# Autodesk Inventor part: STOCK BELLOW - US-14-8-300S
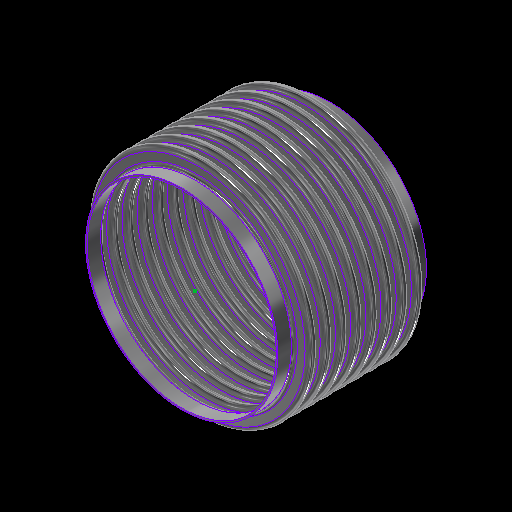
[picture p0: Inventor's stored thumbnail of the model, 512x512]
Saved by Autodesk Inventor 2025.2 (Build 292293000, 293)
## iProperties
Category: 16 GA (0.060 THICK)
RuleStatus: InUse
Created: 2024-01
Part Number: STOCK BELLOW - US-14-8-300S
Project: =STOCK BELLOWS: <Stock Number><SFILL>
Material: ASTM A240-304
Description: =STOCK BELLOWS: <Stock Number>, <SID_> I.D., <SOD_> O.D., <SPLY_> PLY, <Category>, <SNET_CONS> CONS.<PITCH_><STANGENT_> TANGENT<SFILL>
Document SubType Name: Sheet Metal
Designer: GS
Stock Number: U.S-14-8-300S
Surface Area: 15703.3 cm^2
Volume: 2361.78 cm^3
Sheet Metal Rule: Default
Appearance: STAINLESS STEEL
Mass: 19029.5 g
Density: 8.05729 g/cm^3
THK: 0.036
ID: 3.500
OD: 4.250
CONS_: 2
PITCH: 0.500
TANGENT: 0.500
BELLOWS_UPSET: 0.000
d79: 1.000
d82: 1.000
d83: 26.000
d84: 24.000
d174: 8
d214: 8
STHK_: 0.060
SID_: 14.000
SOD_: 16.500
SPITCH_: 1.125
STANGENT__: 1.000
SBELLOWS_UPSET_: 0.000
SDIFF_TAN: 1.000
d252: 2
d275: 2
d287: 0.050
d289: 0.500
d290: 0.000
SOD_NECK: 14 1/4
PLY: 1
PSET: 4.178
PBAR: 1.035
COUNTER: 1.500
NET_TUBE: 3.071
CONS: 2
S_CONS: 0
NET_CONS: 2
ID_M: 88.90 mm
OD_M: 107.95 mm
THK_M: 0.91 mm
ID_U: 3.500 in
OD_U: 4.250 in
THK_U: 0.036 in
TANGENT2: 0.500
TAN_TO_TAN: 1.000 in
d80: 2.571
d81: 10
SID: 2.375
SCONS_: 8
SPITCH: 0.250
STANGENT_: 1.000
SBELLOWS_UPSET: 0.000
SNET_CONS: 8
SS_CONS: 0
SCONS: 8
d190: 8
d191: 1
d192: 1
d193: 8
d194: 0
SIZE: 14.00
PRESSURE: 300
d230: 8
STANGENT: 4.000
SPLY_: 2
d233: 8
d234: 0
d263: 2
d265: 1
d268: 2
d269: 0
d286: 2
d288: 1
d291: 2
d292: 0
SREROLL: 0.750
BLETP: 0.000 ul
PRES_Copy: 85
MATTABLE: 20 GA (0.036 THICK)
PART_NUMBER: U.S-14-8-300S
PITCH_: =, <SPITCH_> PITCH,
CFILL: .
SFILL: .
MESH: ,
COMP: 1.55
EXT: 0.78
LAT: 0.30
ANG: 573
ASR: 8185
LSR: 35251
ANSR: 4153
PRES: 300
COMPM: 15.5
EXTM: 7.75
LATM: 3.00
ASRM: 1433.439
PRESM: 20.684
LSRM: 6173.508
ANSRM: 727.315
TEMPMIN: 20
TEMPMAX: 800
TEMPMINM: -7
TEMPMAXM: 427
WEIGHTM: 19.030
WEIGHT: 41.953
Author: GS
Keywords: 20 GA (0.036 THICK)
Comments: =STOCK BELLOW - <STOCK NUMBER>
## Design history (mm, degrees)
sketch "Sketch2"
  geometry: L1 (0, -177.245)-(0, 562.856) reference; L2 (45.364, 0)-(44.45, 0); L3 (48.082, -2.718)-(50.343, -2.718); L4 (48.082, -3.632)-(50.343, -3.632); L5 (50.343, -9.982)-(48.082, -9.982); L6 (50.343, -9.068)-(48.082, -9.068); L7 (45.364, -12.7)-(44.45, -12.7); L8 (48.082, 0)-(48.082, -12.7); L9 (50.343, -6.35)-(53.975, -6.35); L10 (44.45, 0)-(44.45, -12.7); L11 (20.376, 102.841)-(20.376, 101.926); L12 (58.262, 457.127)-(58.262, 349.177); L13 (58.262, 444.427)-(58.262, 336.477); L14 (93.133, -58.817)-(93.133, -71.517); L15 (118.746, -66.401)-(118.746, -66.401); L16 (50.343, -9.068)-(50.343, -9.982); L17 (48.082, -9.068)-(48.082, -9.982); L18 (48.082, -9.525)-(50.343, -9.525); L19 (53.975, 0)-(53.975, -12.7); L20 (-50.343, -9.068)-(-50.343, -9.982); L21 (-50.343, -2.718)-(-48.082, -2.718); L22 (-50.343, -3.632)-(-48.082, -3.632); L23 (-48.082, -9.068)-(-50.343, -9.068); L24 (-50.343, -9.525)-(-48.082, -9.525); L25 (-48.082, -9.982)-(-50.343, -9.982); L26 (-48.082, -9.068)-(-48.082, -9.982); L27 (-44.45, 0.653)-(-44.45, -12.047); L28 (-48.082, -6.35)-(-44.45, -6.35); L29 (-50.343, 0.653)-(-50.343, -12.7); L30 (-53.061, 0)-(-53.975, 0); L31 (-53.975, 0)-(-53.975, -12.7); L32 (-53.061, -12.7)-(-53.975, -12.7); A1 r 2.718 centre (48.082, 0) between (45.364, 0) and (48.082, -2.718); A2 r 3.632 centre (48.082, 0) between (44.45, 0) and (48.082, -3.632); A3 r 3.632 centre (50.343, -6.35) between (50.343, -9.982) and (50.343, -2.718); A4 r 2.718 centre (50.343, -6.35) between (50.343, -9.068) and (50.343, -3.632); A5 r 2.718 centre (48.082, -12.7) between (48.082, -9.982) and (45.364, -12.7); A6 r 3.632 centre (48.082, -12.7) between (48.082, -9.068) and (44.45, -12.7); A7 r 3.175 centre (50.343, -6.35) between (50.343, -9.525) and (53.518, -6.35); A8 r 3.175 centre (48.082, -12.7) between (48.082, -9.525) and (44.907, -12.7); A9 r 2.718 centre (-50.343, -12.7) between (-50.343, -9.982) and (-53.061, -12.7); A10 r 2.718 centre (-48.082, -6.35) between (-48.082, -9.068) and (-48.082, -3.632); A11 r 3.175 centre (-48.082, -6.35) between (-48.082, -9.525) and (-44.907, -6.35); A12 r 3.632 centre (-48.082, -6.35) between (-48.082, -9.982) and (-48.082, -2.718); A13 r 3.175 centre (-50.343, -12.7) between (-50.343, -9.525) and (-53.518, -12.7); A14 r 3.632 centre (-50.343, -12.7) between (-50.343, -9.068) and (-53.975, -12.7); A15 r 2.718 centre (-50.343, 0) between (-53.061, 0) and (-50.343, -2.718); A16 r 3.632 centre (-50.343, 0) between (-53.975, 0) and (-50.343, -3.632); 10 further points
  constraints: 62 end point, 38 point on circle, 20 tangent, 16 centre point, 12 parallel, 9 midpoint, 7 vertical, 6 coincident, 6 concentric, 6 point on line, 4 equal radius, 4 perpendicular, 3 horizontal, 1 collinear, 1 horizontal alignment, 10 other
  dimensions: "THK" = 0.9144 distance of L11.start L11.end; "ID" = 88.9 distance of L11.end point (20.376, 13.026); "OD" = 107.95 distance of L12.start L12.end; "PITCH" = 12.7 distance of L12.start L13.start; "TANGENT" = 12.7 distance of L14.start L14.end; "BELLOWS_UPSET" = 0 distance of L15.start L15.end; "d43" = 88.9 diameter of L10 L1 (= ID); "d44" = 107.95 diameter of L9.end L1 (= OD); "d45" = 0.9144 distance between parallel lines of L5 L6 (computed from THK, PLY); "d46" = 3.6322 radius of A3 (computed from PITCH, THK, PLY); "UPSET_PITCH" = 12.7 distance of L2.end L7.end (derived); "SIDEWALL_ANGLE" = 360 deg dimension on L3 L9 (derived); "CON_GAP" = 5.4356 distance of point (48.082, -9.068) point (48.082, -3.632) (derived); "TAN1" = 4.98728 dimension on A8 (derived); "TAN2" = 4.98728 dimension on A7 (derived); "LEG1" = 2.2606 distance of L18.start L18.end (derived); "d278" = 0.9144 distance between parallel lines of L25 L23 (derived); "d279" = 3.6322 radius of A12 (derived); "d280" = 12.7 distance of L30.end L31.end (derived); "d281" = 360 deg dimension on L21 L28 (derived); "d282" = 5.4356 distance of point (-50.343, -9.068) point (-50.343, -3.632) (derived); "d283" = 4.98728 dimension on A13 (derived); "d284" = 4.98728 dimension on A11 (derived); "d285" = 2.2606 distance of L24.start L24.end (derived); "d293" = 88.9 diameter of L27 L1 (derived); "d294" = 107.95 diameter of L31 L1 (derived)
  node "Sketch Rectangular Pattern1" dims "d31" = 25.4, "ID" = 88.9
  node "Sketch Rectangular Pattern2" dims "d39" = 25.4, "PITCH" = 12.7
revolve "CONS" stored, may be unused: angle "d48" = 90 deg
node "BELLOW MIDPLANE"
pattern_linear "Rectangular Pattern2" dims "d52" = 12.7 (= UPSET_PITCH)
sketch "Sketch5"
  geometry: C1 r 45.364 at (0, 0) reference; C2 r 44.45 at (0, 0) reference
extrude "TANGENT" new body sketch "Sketch5" distance "d53" = 12.7 (= TANGENT); taper "d54" = 0 deg
revolve "SAMETAN" stored, may be unused: angle "d65" = 90 deg
revolve "DIFFTAN" stored, may be unused: angle "d70" = 90 deg
sketch "Sketch9"
  geometry: L1 (53.319, 0)-(-53.319, 0) reference; L2 (0, -17.78)-(0, 17.78) reference; L3 (38.085, 0)-(-38.085, 0); L4 (38.085, -11.906)-(38.085, 11.906); L5 (25.385, -11.906)-(25.385, 11.906); L6 (13.15, 11.906)-(13.15, -11.906); L7 (-25.385, -11.906)-(-25.385, 11.906); L8 (-38.085, -11.906)-(-38.085, 11.906); L9 (37.291, -11.906)-(37.291, 11.906); L10 (38.085, -11.906)-(37.291, -11.906); L11 (38.085, 11.906)-(37.291, 11.906); L12 (13.546, 11.906)-(12.753, 11.906); L13 (12.753, 11.906)-(12.753, -11.906); L14 (12.753, -11.906)-(13.546, -11.906); L15 (13.546, -11.906)-(13.546, 11.906); L16 (-13.546, 11.906)-(-13.546, -11.906); L17 (-13.15, 11.906)-(-13.15, -11.906); L18 (-13.546, -11.906)-(-12.753, -11.906); L19 (-12.753, -11.906)-(-12.753, 11.906); L20 (-12.753, 11.906)-(-13.546, 11.906); L21 (-38.085, -11.906)-(-37.291, -11.906); L22 (-37.291, -11.906)-(-37.291, 11.906); L23 (-37.291, 11.906)-(-38.085, 11.906); L24 (-38.085, 11.906)-(-38.085, -11.906); L25 (38.085, -0.397)-(-38.085, -0.397); L26 (-38.085, -0.397)-(-38.085, 0.397); L27 (-38.085, 0.397)-(38.085, 0.397); L28 (38.085, 0.397)-(38.085, -0.397); L29 (-38.085, 11.906)-(38.085, 11.906); L30 (38.085, 11.906)-(38.085, 12.7); L31 (38.085, 12.7)-(-38.085, 12.7); L32 (-38.085, 12.7)-(-38.085, 11.906); L33 (38.085, -11.906)-(-38.085, -11.906); L34 (-38.085, -11.906)-(-38.085, -12.7); L35 (-38.085, -12.7)-(38.085, -12.7); L36 (38.085, -12.7)-(38.085, -11.906); 30 further points
  constraints: 68 end point, 13 midpoint, 13 parallel, 8 horizontal, 7 perpendicular, 6 equal length, 3 point on line, 2 vertical, 14 other
  dimensions: "d115" = 23.8125 distance of L4.start L4.end (derived); "d116" = 12.7 distance between parallel lines of L4 L5 (derived); "d117" = 12.23516 distance between parallel lines of L5 L6 (derived); "d125" = 38.53427 distance between parallel lines of L7 L6 (derived); "d127" = 12.7 distance between parallel lines of L8 L7 (derived); "d128" = 24.93516 distance between parallel lines of L6 L4 (derived); "d130" = 76.16943 distance between parallel lines of L8 L4 (derived); "RULER_THK" = 0.79375 distance between parallel lines of L4 L9; "d135" = 0.79375 distance of L13.end L14.end (derived); "d138" = 26.29911 distance of L13.end L16.end (derived); "d143" = 0.79375 distance of L22.end L8.end (derived); "d144" = 0.79375 distance between parallel lines of L27 L25 (derived)
extrude "RULER" join sketch "Sketch9" distance "d149" = 0.79375 (derived); taper "d150" = 0 deg
extrude "BARS" join sketch "Sketch9" distance "d151" = 0.79375 (derived); taper "d152" = 0 deg
pattern_linear "Rectangular Pattern4" dims "d155" = 26.29911 (derived)
sketch "Sketch13"
  geometry: L1 (93.149, -52.467)-(93.149, -77.867); L2 (180.848, 0)-(177.8, 0); L3 (180.848, -28.575)-(177.8, -28.575); L4 (200.882, -22.955)-(186.468, -22.955); L5 (200.882, -19.907)-(186.468, -19.907); L6 (200.882, -14.287)-(209.55, -14.287); L7 (186.468, -5.62)-(200.882, -5.62); L8 (186.468, 0)-(186.468, -28.575); L9 (177.8, 0)-(177.8, -28.575); L10 (58.254, -77.331)-(58.254, -496.431); L11 (58.254, -105.906)-(58.254, -525.006); L12 (58.254, -163.056)-(58.254, -582.156); L13 (58.254, -191.631)-(58.254, -610.731); L14 (58.254, -220.206)-(58.254, -639.306); L15 (58.254, -248.781)-(58.254, -667.881); L16 (58.254, -277.356)-(58.254, -696.456); L17 (58.254, -134.481)-(58.254, -553.581); L18 (20.376, 103.45)-(20.376, 101.926); L19 (186.468, -8.668)-(200.882, -8.668); L20 (0, -856.437)-(0, 263.431) reference; L21 (-41.91, 0)-(251.46, 0) reference; A1 r 5.62 centre (186.468, 0) between (180.848, 0) and (186.468, -5.62); A2 r 5.62 centre (186.468, -28.575) between (186.468, -22.955) and (180.848, -28.575); A3 r 8.668 centre (186.468, -28.575) between (186.468, -19.907) and (177.8, -28.575); A4 r 5.62 centre (200.882, -14.287) between (200.882, -19.907) and (200.882, -8.668); A5 r 8.668 centre (200.882, -14.287) between (200.882, -22.955) and (200.882, -5.62); A6 r 8.668 centre (186.468, 0) between (177.8, 0) and (186.468, -8.668); 6 further points; 1 other entity
  constraints: 38 end point, 15 point on circle, 9 tangent, 6 centre point, 6 parallel, 5 vertical alignment, 4 point on line, 4 vertical, 3 coincident, 3 concentric, 2 collinear, 2 equal radius, 1 horizontal, 1 perpendicular, 23 other
  dimensions: "SBELLOWS_UPSET_" = 0 distance of point (118.762, -66.401) point (118.762, -66.401); "STOTAL_THK_BELLOW__" = 3.048 distance between parallel lines of L4 L5 (derived); "d224" = 8.66775 radius of A5 (derived); "d225" = 28.575 distance of L2.end L3.end (derived); "SSIDEWALL_ANGLE_" = 360 deg dimension on L7 L6 (derived); "SSCON_GAP_" = 11.2395 distance of point (186.468, -19.907) point (186.468, -8.668) (derived); "d235" = 355.6 diameter of L9 L20 (derived); "d236" = 419.1 diameter of L6.end L20 (derived)
  node "Sketch Rectangular Pattern4" dims "d228" = 25.4
  node "Sketch Rectangular Pattern5" dims "d229" = 25.4
revolve "SBELLOW" stored, may be unused: angle "d197" = 90 deg
pattern_linear "Rectangular Pattern5" dims "d204" = 28.575 (derived)
revolve "STANGENT" stored, may be unused: angle "d240" = 90 deg
revolve "SSAMETAN" stored, may be unused: angle "d241" = 90 deg
revolve "SDIFFTAN" stored, may be unused: angle "d246" = 90 deg
revolve "INVCON" stored, may be unused: angle "d295" = 90 deg
pattern_linear "Rectangular Pattern6" dims "d298" = 12.7 (derived)
revolve "INVTANGENT" stored, may be unused: angle "d302" = 90 deg
revolve "INVSAMETAN" stored, may be unused: angle "d307" = 90 deg
revolve "INVDIFFTAN" stored, may be unused: angle "d312" = 90 deg
sketch "ID BELLOW MOUNT CALC"
  geometry: L1 (44.45, 0)-(38.1, 0); L2 (38.1, 0)-(38.1, 12.7); L3 (38.1, 12.7)-(44.45, 12.7); L4 (44.45, 12.7)-(44.45, 0); L5 (36.513, 12.7)-(35.598, 12.7); L6 (35.598, 12.7)-(35.598, 0); L7 (35.598, 0)-(36.513, 0); L8 (36.513, 0)-(36.513, 12.7); L9 (0, -2.54)-(0, 15.24) reference; L10 (-8.89, 0)-(53.34, 0) reference; 1 further point
  constraints: 16 end point, 5 parallel, 2 collinear, 2 horizontal, 2 perpendicular
  dimensions: "d314" = 12.7 distance of L5.end L6.end (derived); "d315" = 0.9144 distance of L5.start L5.end (derived); "IG" = 1.5875 distance between parallel lines of L2 L8; "PIPE_OD" = 88.9 diameter of L4 L9; "PIPE_WALL" = 6.35 distance of L2.end L3.end; "ID_MT_BELLOW" = 71.1962 diameter of L6 L9 (derived)
revolve "CFILL" stored, may be unused: angle "d320" = 90 deg
pattern_linear "Rectangular Pattern7" dims "d323" = 12.7 (derived)
revolve "SFILL" stored, may be unused: angle "d324" = 90 deg
pattern_linear "Rectangular Pattern8" dims "d327" = 28.575 (derived)
node "STOCK BELLOW MIDPLANE"
node "BELLOW"
sketch "Sketch6"
  geometry: L1 (-12.7, 45.364)-(0, 45.364); L2 (0, 45.364)-(0, 44.45); L3 (0, 44.45)-(-12.7, 44.45); L4 (-12.7, 44.45)-(-12.7, 45.364); L5 (10.16, 0)-(-60.96, 0) reference; L6 (-38.1, -89.422)-(-38.1, 153.44) reference; 1 further point
  constraints: 8 end point, 2 parallel, 1 horizontal, 1 perpendicular
  dimensions: "d61" = 12.7 distance of L2.end L3.end (derived); "d62" = 0.9144 distance of L1.end L2.end (derived); "d63" = 88.9 diameter of L3 L5 (derived); "d64" = 25.4 distance between parallel lines of L4 L6 (derived)
sketch "Sketch12"
  geometry: 1 further point
sketch "Sketch14"
  geometry: L1 (-25.4, 180.848)-(0, 180.848); L2 (0, 180.848)-(0, 177.8); L3 (0, 177.8)-(-25.4, 177.8); L4 (-25.4, 177.8)-(-25.4, 180.848); L5 (5.08, 0)-(-30.48, 0) reference; L6 (0, -36.17)-(0, 217.018) reference; 1 further point
  constraints: 8 end point, 2 parallel, 1 collinear, 1 horizontal, 1 perpendicular
  dimensions: "d237" = 3.048 distance of L3.end L1.start (derived); "d238" = 355.6 diameter of L3 L5 (derived); "d239" = 25.4 distance of L1.start L1.end (derived); "SOD_NECK" = 361.696 diameter of L1 L5 (derived)
sketch "Sketch15"
  geometry: L1 (-36.17, 0)-(217.018, 0) reference; L2 (177.8, -228.6)-(180.848, -228.6); L3 (180.848, -228.6)-(180.848, -254); L4 (180.848, -254)-(177.8, -254); L5 (177.8, -254)-(177.8, -228.6); L6 (0, -307.34)-(0, 66.04) reference; 1 further point
  constraints: 8 end point, 2 parallel, 1 horizontal, 1 perpendicular
  dimensions: "d205" = 25.4 distance of L4.end L2.start (derived); "d206" = 3.048 distance of L3.end L4.end (derived); "d207" = 355.6 diameter of L5 L6 (derived); "d208" = 228.6 distance between parallel lines of L1 L2 (derived)
node "TANGENT_"
node "SAME_TAN"
sketch "Sketch8"
  geometry: L1 (45.364, -25.4)-(44.45, -25.4); L2 (44.45, -25.4)-(44.45, -38.1); L3 (44.45, -38.1)-(45.364, -38.1); L4 (45.364, -38.1)-(45.364, -25.4); L5 (0, -48.26)-(0, 22.86) reference; L6 (-89.422, 0)-(153.44, 0) reference; 1 further point
  constraints: 8 end point, 2 parallel, 1 horizontal, 1 perpendicular
  dimensions: "d66" = 88.9 diameter of L2 L5 (derived); "TOTAL_THK_BELLOW" = 0.9144 distance of L2.end L3.end (derived); "d68" = 25.4 distance between parallel lines of L1 L6 (derived); "d69" = 12.7 distance of L1.end L2.end (derived)
node "DIFF_TAN"
node "Sketch Rectangular Pattern3" dims "d138" = 26.29911 (derived), "d141" = 25.4
node "SBELLOW_"
node "STANGENT_"
node "SSAME_TAN"
sketch "Sketch16"
  geometry: L1 (180.848, -228.6)-(177.8, -228.6); L2 (177.8, -228.6)-(177.8, -254); L3 (177.8, -254)-(180.848, -254); L4 (180.848, -254)-(180.848, -228.6); L5 (0, -307.34)-(0, 66.04) reference; L6 (-36.17, 0)-(217.018, 0) reference; 1 further point
  constraints: 8 end point, 2 parallel, 1 horizontal, 1 perpendicular
  dimensions: "SDIFF_TAN" = 25.4 distance of L3.end L1.start; "d243" = 3.048 distance of L2.end L3.end (derived); "d244" = 228.6 distance between parallel lines of L1 L6 (derived); "d245" = 355.6 diameter of L2 L5 (derived)
node "SDIFF_TAN"
body "Solid15"
sketch "Sketch17"
  geometry: L1 (53.975, 12.7)-(53.061, 12.7); L2 (53.061, 12.7)-(53.061, 0); L3 (53.061, 0)-(53.975, 0); L4 (53.975, 0)-(53.975, 12.7); L5 (0, -2.54)-(0, 15.24) reference; L6 (-10.795, 0)-(64.77, 0) reference; 2 further points
  constraints: 8 end point, 2 parallel, 1 horizontal, 1 midpoint, 1 perpendicular, 1 point on line
  dimensions: "INVTANGENT" = 12.7 distance of L3.end L1.start (derived); "d300" = 0.9144 distance of L1.start L1.end (derived); "d301" = 107.95 diameter of L4 L5 (derived)
body "Solid16"
sketch "Sketch18"
  geometry: L1 (53.975, -25.4)-(53.061, -25.4); L2 (53.061, -25.4)-(53.061, -38.1); L3 (53.061, -38.1)-(53.975, -38.1); L4 (53.975, -38.1)-(53.975, -25.4); L5 (-10.795, 0)-(64.77, 0) reference; L6 (0, -48.26)-(0, 22.86) reference; 1 further point
  constraints: 8 end point, 2 parallel, 1 horizontal, 1 perpendicular
  dimensions: "d303" = 25.4 distance between parallel lines of L1 L5 (derived); "d304" = 12.7 distance of L3.end L1.start (derived); "d305" = 0.9144 distance of L2.end L3.end (derived); "d306" = 107.95 diameter of L4 L6 (derived)
body "Solid17"
sketch "Sketch19"
  geometry: L1 (53.975, -25.4)-(53.061, -25.4); L2 (53.061, -25.4)-(53.061, -38.1); L3 (53.061, -38.1)-(53.975, -38.1); L4 (53.975, -38.1)-(53.975, -25.4); L5 (0, -48.26)-(0, 22.86) reference; L6 (-10.795, 0)-(64.77, 0) reference; 1 further point
  constraints: 8 end point, 2 parallel, 1 horizontal, 1 perpendicular
  dimensions: "d308" = 12.7 distance of L1.end L2.end (derived); "d309" = 107.95 diameter of L4 L5 (derived); "d310" = 0.9144 distance of L2.end L3.end (derived); "d311" = 25.4 distance between parallel lines of L1 L6 (derived)
body "Solid18"
body "Solid19"
body "Solid20"
other parameters: "BMPL" = -114.3, "PSET" = 106.1212 (computed from OD, THK, PLY) [user parameter], "PBAR" = 26.29911 (= 0.570796 x PITCH + OD - ID) [user parameter; used in 1 equation term], "COUNTER" = 15 [user parameter], "NET_TUBE" = 77.99823 (computed from CONS_, PBAR, TANGENT) [user parameter], "S_CONS" = 0 [user parameter; used in 1 equation term], "ID_M" = 88.9 (= ID) [user parameter], "OD_M" = 107.95 (= OD) [user parameter], "THK_M" = 0.9144 (= THK) [user parameter], "ID_U" = 88.9 (= ID) [user parameter], "OD_U" = 107.95 (= OD) [user parameter], "THK_U" = 0.9144 (= THK) [user parameter], "D_UNITS" = 0 [user parameter], "TANGENT2" = 12.7 [user parameter], "TAN_TO_TAN" = 25.4 [user parameter], "OD_NECK" = 90.7288 [user parameter], "d79" = 25.4, "d80" = 65.29823 [user parameter], "d82" = 25.4, "d83" = 660.4, "d84" = 609.6, "sa_0" = 4, "FRAME_THK" = 0.79375 [user parameter], "CON_FLAT" = 12.23516 [user parameter], "SID" = 60.325 [user parameter], "SPITCH" = 6.35 [user parameter], "STANGENT_" = 25.4 [user parameter], "SBELLOWS_UPSET" = 0 [user parameter], "SS_CONS" = 0 [user parameter], "STAN_TO_TAN_" = 228.6 [user parameter], "d100" = 3.048 [user parameter], "d191" = 25.4 [user parameter], "d194" = 0 [user parameter], "STANGENT" = 101.6 [user parameter], "d234" = 0 [user parameter], "SUPSET_PITCH_" = 28.575 [user parameter], "d269" = 0 [user parameter], "d287" = 1.27, "d289" = 12.7, "d290" = 0, "d292" = 0 [user parameter], "Thickness" = 3.048 (derived), "KFactor" = 4.4, "BendRadius" = 3.048 (derived), "BendReliefWidth" = 3.048 (derived), "BendReliefDepth" = 1.524 (derived), "CornerReliefSize" = 12.192 (derived), "SeamGap" = 0.00508, "MinimumRemnant" = 6.096 (derived), "TransitionRadius" = 3.048 (derived), "JacobiRadiusSize" = 3.048 (derived), "GapSize" = 3.048 (derived), "SREROLL" = 19.05 [user parameter], "CUR_STK_PITCH" = 28.575 [user parameter], "d328" = -114.3 (derived), "ASR" = 81850 [user parameter], "LSR" = 352510 [user parameter], "ANSR" = 41530 [user parameter], "BLETP" = 0 [user parameter], "ASRM" = 14334.3905 [user parameter], "PRESM" = 206.83949 [user parameter], "LSRM" = 61735.0763 [user parameter], "ANSRM" = 7273.1489 [user parameter], "TEMPMIN" = 2664.83333 [user parameter], "TEMPMAX" = 6998.16667 [user parameter], "TEMPMINM" = 2664.83333 [user parameter], "TEMPMAXM" = 6998.16667 [user parameter], "WEIGHT" = 190.29503 [user parameter], "WEIGHTM" = 0.1903 [user parameter]
